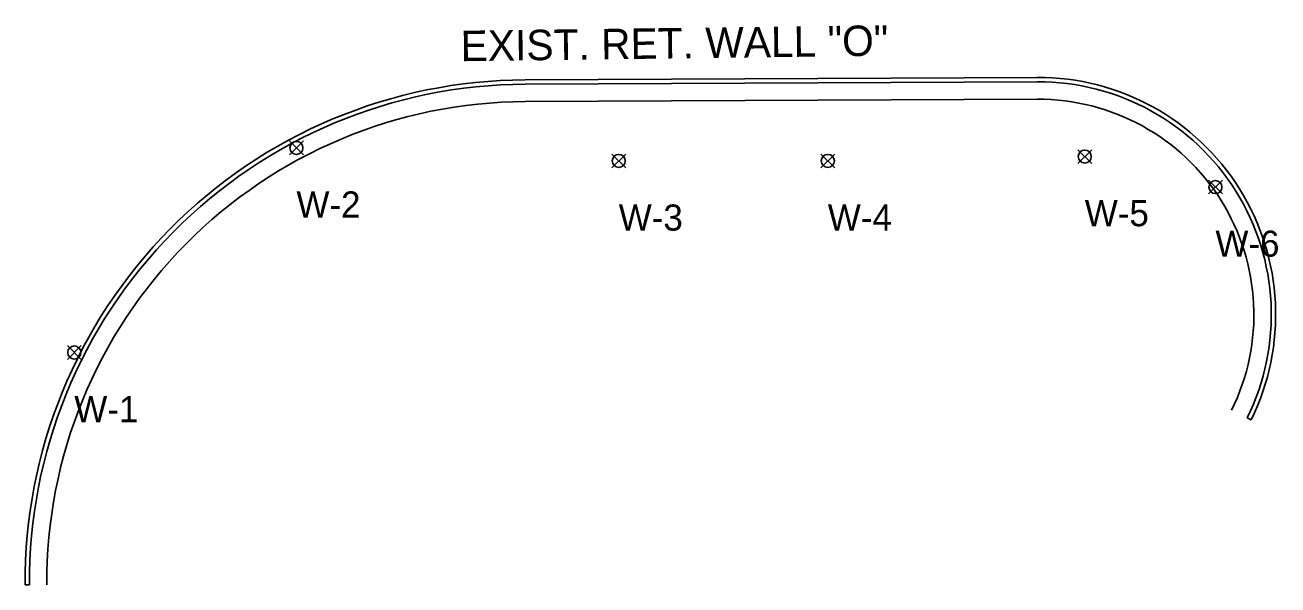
# Model space of a CAD drawing. Extents: x 2145143 to 2153172, y 140167 to 148213.
# Drawn here: x 2150909.3 to 2151197, y 148084.6 to 148213.2 of the extents above; entities that cross this region are included whole.
import ezdxf

# ---------------------------------------------------------------- set-up
doc = ezdxf.new("R2010")
doc.units = 0
for name, color, linetype in [('Default', 7, 'Continuous'), ('FLDBK_Points', 7, 'Continuous'), ('Phase1_Paved Ditch', 7, 'Continuous'), ('PR_Align_Retaining_Wall_O_Txt', 7, 'Continuous'), ('TOPO_Misc', 7, 'Continuous'), ('TOPO_Wall Retaining', 7, 'Continuous')]:
    doc.layers.add(name, color=color, linetype=linetype)

# ---------------------------------------------------------------- blocks, each defined once
blk = doc.blocks.new('BORE')
at = {"layer": 'TOPO_Misc'}
for p, q in [((-0.0318, 0.0318), (0.0318, -0.0318)), ((-0.0318, -0.0318), (0.0318, 0.0318))]:
    blk.add_line(p, q, dxfattribs=at)
blk.add_circle((0, 0), 0.03, dxfattribs=at)

msp = doc.modelspace()

# ---------------------------------------------------------------- linework, layer by layer
at = {"layer": 'Phase1_Paved Ditch'}
msp.add_line((2151141.77, 148196.18), (2151024.18, 148195.64), dxfattribs=at)
for centre, radius, start, end in [((2151024.68, 148085.31), 110.33, 90.2591, 180.3442), ((2151141.99, 148146.68), 49.5, 333.7443, 90.2591)]:
    msp.add_arc(centre, radius, start, end, dxfattribs=at)
at = {"layer": 'TOPO_Wall Retaining'}
for p, q in [((2151141.75, 148201.18), (2151024.16, 148200.64)), ((2151141.75, 148200.18), (2151024.16, 148199.64)), ((2151189.97, 148123.01), (2151190.87, 148122.57)), ((2150909.35, 148084.62), (2150910.35, 148084.62))]:
    msp.add_line(p, q, dxfattribs=at)
for centre, radius, start, end in [((2151024.68, 148085.31), 115.33, 90.2591, 180.3442), ((2151141.99, 148146.68), 54.5, 333.7443, 90.2591), ((2151024.68, 148085.31), 114.33, 90.2591, 180.3442), ((2151141.99, 148146.68), 53.5, 333.7443, 90.2591)]:
    msp.add_arc(centre, radius, start, end, dxfattribs=at)

# ---------------------------------------------------------------- block references
at = {"layer": 'Default', "xscale": 50, "yscale": 50}
for p in [(2150971.66, 148185), (2151045.66, 148182), (2151093.66, 148182), (2151152.66, 148183), (2151182.66, 148176), (2150920.66, 148138)]:
    msp.add_blockref('BORE', p, dxfattribs=at)

# ---------------------------------------------------------------- texts
at = {"layer": 'FLDBK_Points'}
for s, p in [('W-2', (2150971.66, 148169)), ('W-3', (2151045.66, 148166)), ('W-4', (2151093.66, 148166)), ('W-5', (2151152.66, 148167)), ('W-6', (2151182.66, 148160)), ('W-1', (2150920.66, 148122))]:
    msp.add_text(s, height=6, dxfattribs=at).set_placement(p)
at = {"layer": 'PR_Align_Retaining_Wall_O_Txt'}
msp.add_text('EXIST. RET. WALL "O"', height=7, rotation=0.7472, dxfattribs=at).set_placement((2151009.4, 148204.9))

doc.saveas('drawing.dxf')
